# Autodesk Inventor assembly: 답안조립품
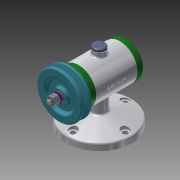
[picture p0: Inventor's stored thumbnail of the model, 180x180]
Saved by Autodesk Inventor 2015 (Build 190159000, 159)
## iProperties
Created: 2018-12
Part Number: 답안조립품
Document SubType Name: Assembly
Designer: now060
Author: now060
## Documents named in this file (15)
- C:\Users\now060\Desktop\481207V1070\답안조립품.iam
- C:\Users\now060\Desktop\481207V1070\V벨트풀리.ipt
- C:\Users\now060\Desktop\481207V1070\키 3 x 3 x 12.ipt
- C:\Users\now060\Desktop\481207V1070\고무캡.ipt
- C:\Users\now060\Desktop\481207V1070\너트 M8.ipt
- 너트 M8.ipt
- C:\Users\now060\Desktop\481207V1070\뒤커버.ipt
- C:\Users\now060\Desktop\481207V1070\베어링 15 x 32 x 9.ipt
- C:\Users\now060\Desktop\481207V1070\답안본체.ipt
- C:\Users\now060\Desktop\481207V1070\볼트 M4 x 12.ipt
- C:\Users\now060\Desktop\481207V1070\스프링와셔 8.ipt
- C:\Users\now060\Desktop\481207V1070\앞커버.ipt
- C:\Users\now060\Desktop\481207V1070\오일 실 15 25 7.ipt
- C:\Users\now060\Desktop\481207V1070\와셔 8x17.ipt
- C:\Users\now060\Desktop\481207V1070\축.ipt
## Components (2 placed, 2 different names)
1. V벨트풀리:1 — 각도:2
2. 고무캡:1
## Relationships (1: Angle 1)
- 각도:2 [Angle]: V벨트풀리:1
